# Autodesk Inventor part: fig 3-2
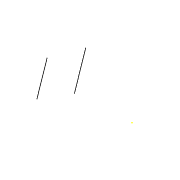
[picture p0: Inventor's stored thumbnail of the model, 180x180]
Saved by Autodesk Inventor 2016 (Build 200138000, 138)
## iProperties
Created: 2011-07
Part Number: fig 3-2
Material: Generic
Document SubType Name: Modeling
Designer: CadCim
Density: 1 g/cm^3
Appearance: Default
Author: CadCim
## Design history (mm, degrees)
sketch "Sketch1"
  geometry: L1 (-29, 4)-(-20, -8); L2 (-16, -0.965)-(-25.943, 12.292); 1 further point
  constraints: 4 end point, 1 parallel, 1 other
